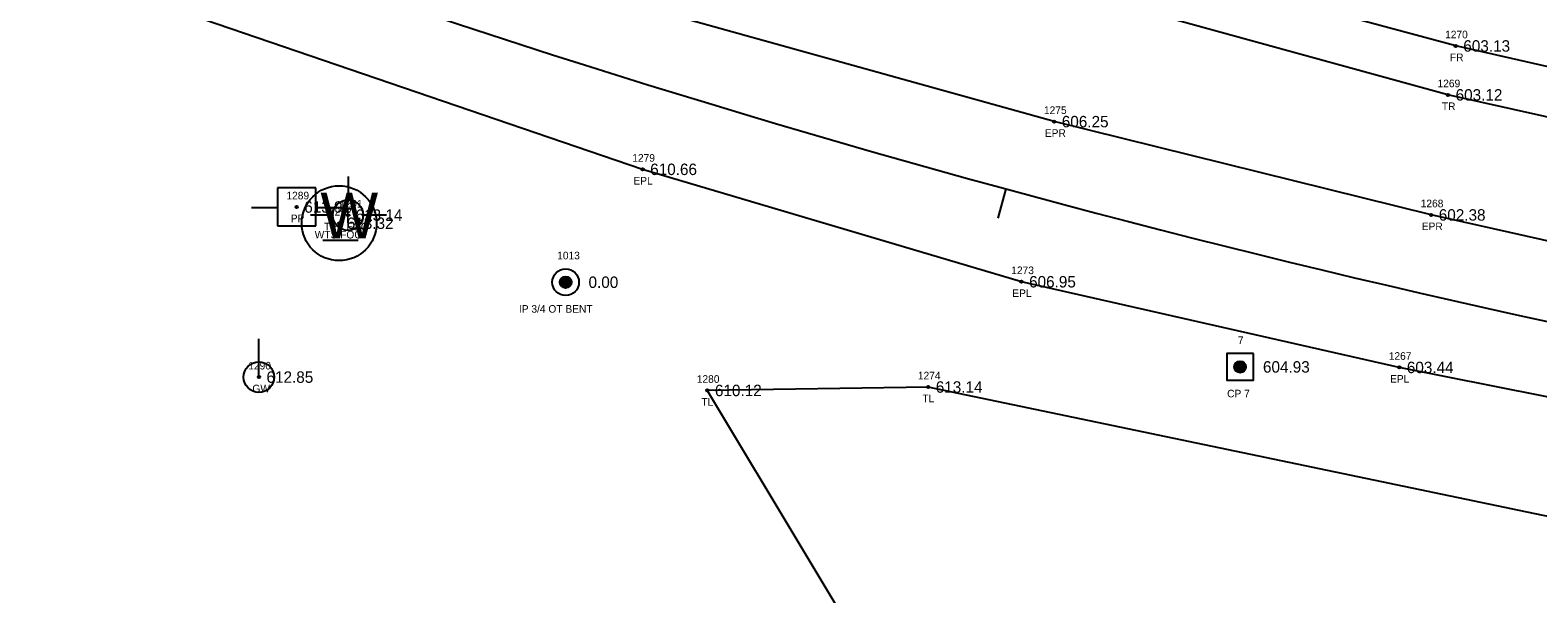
# Model space of a CAD drawing. Extents: x 1529475 to 1532053, y 876698 to 877911.
# Drawn here: x 1530226.7 to 1530424.5, y 877264.8 to 877338.8 of the extents above; entities that cross this region are included whole.
import ezdxf

# ---------------------------------------------------------------- set-up
doc = ezdxf.new("R2010")
doc.units = 0
for name, color, linetype in [('RD_EX_DV_Prop_txCode', 7, 'Continuous'), ('RD_EX_DV_PropPin', 7, 'Continuous'), ('RD_EX_Fence_Other', 7, 'Continuous'), ('RD_EX_Fence_Other_txCode', 7, 'Continuous'), ('RD_EX_Road', 7, 'Continuous'), ('RD_EX_Road_txCode', 7, 'Continuous'), ('RD_EX_TX_DV_Prop_ELEV', 7, 'Continuous'), ('RD_EX_TX_Fence_Other_ELEV', 7, 'Continuous'), ('RD_EX_TX_Road_ELEV', 7, 'Continuous'), ('RD_EX_TX_UT_ELEV', 7, 'Continuous'), ('RD_EX_TX_VEG_ELEV', 7, 'Continuous'), ('RD_EX_UT', 7, 'Continuous'), ('RD_EX_UT_txCode', 7, 'Continuous'), ('RD_EX_VEG', 7, 'Continuous'), ('RD_EX_VEG_txCode', 7, 'Continuous'), ('RD_HC_Cl', 7, 'Continuous'), ('RD_HC_Data_Tic', 7, 'Continuous'), ('RD_HC_Survey', 7, 'Continuous'), ('RD_HC_Survey_ELEV', 7, 'Continuous'), ('RD_HC_Survey_txCode', 7, 'Continuous'), ('RD_SMD_Locator', 7, 'Continuous')]:
    doc.layers.add(name, color=color, linetype=linetype)

msp = doc.modelspace()

# ---------------------------------------------------------------- linework, layer by layer
at = {"layer": 'RD_EX_DV_PropPin'}
for p, q in [((1530296.22, 877305.5), (1530296.22, 877305.9)), ((1530296.26, 877305.4), (1530296.26, 877306)), ((1530296.29, 877305.33), (1530296.29, 877306.07)), ((1530296.33, 877305.27), (1530296.33, 877306.13)), ((1530296.36, 877305.23), (1530296.36, 877306.17)), ((1530296.4, 877305.18), (1530296.4, 877306.21)), ((1530296.43, 877305.15), (1530296.43, 877306.25)), ((1530296.47, 877305.12), (1530296.47, 877306.28)), ((1530296.5, 877305.09), (1530296.5, 877306.31)), ((1530296.54, 877305.07), (1530296.54, 877306.33)), ((1530296.57, 877305.04), (1530296.57, 877306.36)), ((1530296.61, 877305.02), (1530296.61, 877306.38)), ((1530296.64, 877305.01), (1530296.64, 877306.39)), ((1530296.68, 877304.99), (1530296.68, 877306.41)), ((1530296.71, 877304.98), (1530296.71, 877306.42)), ((1530296.75, 877304.97), (1530296.75, 877306.43)), ((1530296.78, 877304.96), (1530296.78, 877306.44)), ((1530296.82, 877304.95), (1530296.82, 877306.45)), ((1530296.85, 877304.95), (1530296.85, 877306.45)), ((1530296.89, 877304.94), (1530296.89, 877306.46)), ((1530296.92, 877304.94), (1530296.92, 877306.46)), ((1530296.96, 877304.94), (1530296.96, 877306.46)), ((1530296.99, 877304.94), (1530296.99, 877306.46)), ((1530297.03, 877304.94), (1530297.03, 877306.46)), ((1530297.06, 877304.95), (1530297.06, 877306.45)), ((1530297.1, 877304.95), (1530297.1, 877306.45)), ((1530297.13, 877304.96), (1530297.13, 877306.44)), ((1530297.17, 877304.97), (1530297.17, 877306.43)), ((1530297.2, 877304.98), (1530297.2, 877306.42)), ((1530297.24, 877304.99), (1530297.24, 877306.41)), ((1530297.27, 877305.01), (1530297.27, 877306.39)), ((1530297.31, 877305.02), (1530297.31, 877306.38)), ((1530297.34, 877305.04), (1530297.34, 877306.36)), ((1530297.38, 877305.07), (1530297.38, 877306.33)), ((1530297.41, 877305.09), (1530297.41, 877306.31)), ((1530297.45, 877305.12), (1530297.45, 877306.28)), ((1530297.48, 877305.15), (1530297.48, 877306.25)), ((1530297.52, 877305.18), (1530297.52, 877306.21)), ((1530297.55, 877305.23), (1530297.55, 877306.17)), ((1530297.59, 877305.27), (1530297.59, 877306.13)), ((1530297.62, 877305.33), (1530297.62, 877306.07)), ((1530297.66, 877305.4), (1530297.66, 877306)), ((1530297.69, 877305.5), (1530297.69, 877305.9))]:
    msp.add_line(p, q, dxfattribs=at)
for radius in [1.75, 0.761]:
    msp.add_circle((1530296.96, 877305.7), radius, dxfattribs=at)
at = {"layer": 'RD_EX_Fence_Other'}
msp.add_lwpolyline([(1530811.24, 877377.37), (1530859.11, 877317.26), (1530840.03, 877318.28), (1530790.63, 877336.24), (1530780.69, 877332.06), (1530773.35, 877330.36), (1530778.53, 877311.65), (1530751.94, 877310.84), (1530704.94, 877310.7), (1530603.15, 877311.86), (1530564.36, 877314.35), (1530514.23, 877318.81), (1530479.67, 877321.7), (1530413.71, 877336.7), (1530368.16, 877348.99), (1530322.52, 877361.53), (1530309.6, 877379.3), (1530304.43, 877399.7)], dxfattribs=at)
at = {"layer": 'RD_EX_Road'}
for points in [[(1530865.35, 877283.66), (1530865.36, 877280.61), (1530815.01, 877277.89), (1530763.54, 877277.33), (1530711.24, 877277.01), (1530660.64, 877277.93), (1530609.51, 877281.74), (1530559.88, 877286.96), (1530511.03, 877294.4), (1530460.35, 877303.35), (1530410.49, 877314.53), (1530361.04, 877326.77), (1530310.59, 877340.83), (1530305.81, 877342.41), (1530288.71, 877347.95), (1530253.55, 877359.27), (1530192.32, 877382.67)], [(1530866.41, 877261.44), (1530852.87, 877260.97), (1530806.23, 877259.4), (1530762.44, 877259.05), (1530711.8, 877259.77), (1530659.89, 877260.87), (1530608.32, 877263.5), (1530557.85, 877268.33), (1530507.29, 877275.71), (1530456.72, 877284.51), (1530406.3, 877294.52), (1530356.75, 877305.76), (1530307.05, 877320.51), (1530246, 877341.34), (1530185.26, 877363.97)]]:
    msp.add_lwpolyline(points, dxfattribs=at)
at = {"layer": 'RD_EX_UT'}
for p, q in [((1530268.41, 877319.57), (1530268.41, 877316.5)), ((1530264.17, 877318.08), (1530259.17, 877318.08)), ((1530259.17, 877318.08), (1530259.17, 877313.08)), ((1530264.17, 877313.08), (1530264.17, 877318.08)), ((1530255.73, 877315.51), (1530259.2, 877315.51)), ((1530264.09, 877315.51), (1530267.73, 877315.51)), ((1530259.17, 877313.08), (1530264.17, 877313.08)), ((1530263.48, 877314.52), (1530266.41, 877314.52)), ((1530270.41, 877314.52), (1530273.48, 877314.52)), ((1530265.12, 877311.23), (1530269.75, 877311.23)), ((1530256.72, 877293.25), (1530256.72, 877298.25))]:
    msp.add_line(p, q, dxfattribs=at)
for centre, radius in [((1530267.25, 877313.44), 4.91), ((1530268.41, 877314.5), 2), ((1530256.72, 877293.25), 2)]:
    msp.add_circle(centre, radius, dxfattribs=at)
at = {"layer": 'RD_EX_VEG'}
for points in [[(1530772.69, 877331.81), (1530751.94, 877310.84), (1530704.94, 877310.7), (1530664.32, 877301.01), (1530564.36, 877314.35), (1530547.76, 877305.07), (1530463.97, 877318.83), (1530412.7, 877330.28), (1530367.19, 877342.84), (1530314.9, 877359.43), (1530309.6, 877379.3), (1530295.63, 877400.8)], [(1530806.62, 877154.57), (1530847.57, 877176.32), (1530815.29, 877240.21), (1530607.98, 877245.85), (1530502.71, 877258.91), (1530344.51, 877291.95), (1530315.54, 877291.5), (1530341.13, 877248.83)]]:
    msp.add_lwpolyline(points, dxfattribs=at)
at = {"layer": 'RD_HC_Cl'}
msp.add_arc((1530728.17, 878687.95), 1420, 249.7768, 272.33207, dxfattribs=at)
at = {"layer": 'RD_HC_Data_Tic'}
msp.add_line((1530354.68, 877317.95), (1530353.63, 877314.09), dxfattribs=at)
at = {"layer": 'RD_HC_Survey'}
for p, q in [((1530384.98, 877293.96), (1530384.98, 877295.21)), ((1530385, 877293.95), (1530385, 877295.23)), ((1530385.03, 877293.93), (1530385.03, 877295.24)), ((1530385.05, 877293.92), (1530385.05, 877295.26)), ((1530385.07, 877293.9), (1530385.07, 877295.27)), ((1530385.1, 877293.89), (1530385.1, 877295.28)), ((1530385.12, 877293.88), (1530385.12, 877295.29)), ((1530385.15, 877293.87), (1530385.15, 877295.3)), ((1530385.17, 877293.86), (1530385.17, 877295.31)), ((1530385.2, 877293.85), (1530385.2, 877295.32)), ((1530385.22, 877293.85), (1530385.22, 877295.33)), ((1530385.25, 877293.84), (1530385.25, 877295.34)), ((1530385.27, 877293.83), (1530385.27, 877295.34)), ((1530385.3, 877293.83), (1530385.3, 877295.35)), ((1530385.32, 877293.83), (1530385.32, 877295.35)), ((1530385.35, 877293.82), (1530385.35, 877295.35)), ((1530385.37, 877293.82), (1530385.37, 877295.35)), ((1530385.4, 877293.82), (1530385.4, 877295.36)), ((1530385.42, 877293.82), (1530385.42, 877295.36)), ((1530385.45, 877293.82), (1530385.45, 877295.36)), ((1530385.47, 877293.82), (1530385.47, 877295.36)), ((1530385.5, 877293.82), (1530385.5, 877295.35)), ((1530385.52, 877293.82), (1530385.52, 877295.35)), ((1530385.54, 877293.83), (1530385.54, 877295.35)), ((1530385.57, 877293.83), (1530385.57, 877295.34)), ((1530385.59, 877293.84), (1530385.59, 877295.34)), ((1530385.62, 877293.84), (1530385.62, 877295.33)), ((1530385.64, 877293.85), (1530385.64, 877295.33)), ((1530385.67, 877293.86), (1530385.67, 877295.32)), ((1530385.69, 877293.87), (1530385.69, 877295.31)), ((1530385.72, 877293.88), (1530385.72, 877295.3)), ((1530385.74, 877293.89), (1530385.74, 877295.29)), ((1530385.77, 877293.9), (1530385.77, 877295.28)), ((1530385.79, 877293.91), (1530385.79, 877295.26)), ((1530385.82, 877293.92), (1530385.82, 877295.25)), ((1530385.84, 877293.94), (1530385.84, 877295.24)), ((1530385.87, 877293.96), (1530385.87, 877295.22)), ((1530385.89, 877293.97), (1530385.89, 877295.2)), ((1530384.68, 877294.41), (1530384.68, 877294.77)), ((1530384.7, 877294.33), (1530384.7, 877294.85)), ((1530384.73, 877294.27), (1530384.73, 877294.91)), ((1530384.75, 877294.22), (1530384.75, 877294.96)), ((1530384.78, 877294.17), (1530384.78, 877295)), ((1530384.8, 877294.14), (1530384.8, 877295.04)), ((1530384.83, 877294.11), (1530384.83, 877295.07)), ((1530384.85, 877294.08), (1530384.85, 877295.1)), ((1530384.88, 877294.05), (1530384.88, 877295.13)), ((1530384.9, 877294.03), (1530384.9, 877295.15)), ((1530384.93, 877294), (1530384.93, 877295.17)), ((1530384.95, 877293.98), (1530384.95, 877295.19)), ((1530385.92, 877293.99), (1530385.92, 877295.18)), ((1530385.94, 877294.01), (1530385.94, 877295.16)), ((1530385.97, 877294.04), (1530385.97, 877295.14)), ((1530385.99, 877294.06), (1530385.99, 877295.11)), ((1530386.02, 877294.09), (1530386.02, 877295.08)), ((1530386.04, 877294.12), (1530386.04, 877295.05)), ((1530386.06, 877294.16), (1530386.06, 877295.02)), ((1530386.09, 877294.2), (1530386.09, 877294.98)), ((1530386.11, 877294.24), (1530386.11, 877294.93)), ((1530386.14, 877294.3), (1530386.14, 877294.88)), ((1530386.16, 877294.36), (1530386.16, 877294.81)), ((1530386.19, 877294.48), (1530386.19, 877294.7))]:
    msp.add_line(p, q, dxfattribs=at)
msp.add_lwpolyline([(1530387.18, 877296.34), (1530383.68, 877296.34), (1530383.68, 877292.84), (1530387.18, 877292.84)], close=True, dxfattribs=at)
msp.add_circle((1530385.43, 877294.59), 0.769, dxfattribs=at)
at = {"layer": 'RD_SMD_Locator'}
for centre in [(1530413.71, 877336.7), (1530412.7, 877330.28), (1530361.04, 877326.77), (1530307.05, 877320.51), (1530261.67, 877315.57), (1530267.25, 877313.44), (1530268.41, 877314.5), (1530410.49, 877314.53), (1530296.96, 877305.7), (1530356.75, 877305.76), (1530256.72, 877293.25), (1530385.43, 877294.59), (1530406.3, 877294.52), (1530315.54, 877291.5), (1530344.51, 877291.95)]:
    msp.add_circle(centre, 0.15, dxfattribs=at)

# ---------------------------------------------------------------- texts
at = {"layer": 'RD_EX_DV_Prop_txCode'}
for s, p in [('1013', (1530295.85, 877308.7)), ('IP 3/4 OT BENT', (1530290.83, 877301.7))]:
    msp.add_text(s, height=1, dxfattribs=at).set_placement(p)
at = {"layer": 'RD_EX_Fence_Other_txCode'}
for s, p in [('1270', (1530412.32, 877337.7)), ('FR', (1530412.95, 877334.7))]:
    msp.add_text(s, height=1, dxfattribs=at).set_placement(p)
at = {"layer": 'RD_EX_Road_txCode'}
for s, p in [('1275', (1530359.7, 877327.77)), ('EPR', (1530359.82, 877324.77)), ('1279', (1530305.7, 877321.51)), ('EPL', (1530305.85, 877318.51)), ('1268', (1530409.12, 877315.53)), ('EPR', (1530409.26, 877312.53)), ('1273', (1530355.41, 877306.76)), ('EPL', (1530355.55, 877303.76)), ('1267', (1530404.93, 877295.52)), ('EPL', (1530405.1, 877292.52))]:
    msp.add_text(s, height=1, dxfattribs=at).set_placement(p)
at = {"layer": 'RD_EX_TX_DV_Prop_ELEV'}
msp.add_text('0.00', height=1.5, dxfattribs=at).set_placement((1530299.96, 877304.95))
at = {"layer": 'RD_EX_TX_Fence_Other_ELEV'}
msp.add_text('603.13', height=1.5, dxfattribs=at).set_placement((1530414.71, 877335.95))
at = {"layer": 'RD_EX_TX_Road_ELEV'}
for s, p in [('606.25', (1530362.04, 877326.02)), ('610.66', (1530308.05, 877319.76)), ('602.38', (1530411.49, 877313.78)), ('606.95', (1530357.75, 877305.01)), ('603.44', (1530407.3, 877293.77))]:
    msp.add_text(s, height=1.5, dxfattribs=at).set_placement(p)
at = {"layer": 'RD_EX_TX_UT_ELEV'}
for s, p in [('613.14', (1530269.41, 877313.75)), ('613.32', (1530268.25, 877312.69)), ('612.85', (1530257.72, 877292.5))]:
    msp.add_text(s, height=1.5, dxfattribs=at).set_placement(p)
at = {"layer": 'RD_EX_TX_VEG_ELEV'}
for s, p in [('603.12', (1530413.7, 877329.53)), ('610.12', (1530316.54, 877290.75)), ('613.14', (1530345.51, 877291.2))]:
    msp.add_text(s, height=1.5, dxfattribs=at).set_placement(p)
at = {"layer": 'RD_EX_UT'}
for s, height, p in [('W', 6, (1530264.79, 877311.44)), ('T', 2, (1530267.57, 877313.45))]:
    msp.add_text(s, height=height, dxfattribs=at).set_placement(p)
at = {"layer": 'RD_EX_UT_txCode'}
for s, p in [('1289', (1530260.33, 877316.57)), ('1292', (1530265.91, 877314.44)), ('1291', (1530267.35, 877315.5)), ('PP', (1530260.9, 877313.57)), ('TPP FOC', (1530265.26, 877312.5)), ('WTS FOC', (1530264.04, 877311.44)), ('1290', (1530255.33, 877294.25)), ('GW', (1530255.87, 877291.25))]:
    msp.add_text(s, height=1, dxfattribs=at).set_placement(p)
at = {"layer": 'RD_EX_VEG_txCode'}
for s, p in [('1269', (1530411.33, 877331.28)), ('TR', (1530411.9, 877328.28)), ('1280', (1530314.16, 877292.5)), ('1274', (1530343.16, 877292.95)), ('TL', (1530314.77, 877289.5)), ('TL', (1530343.74, 877289.95))]:
    msp.add_text(s, height=1, dxfattribs=at).set_placement(p)
at = {"layer": 'RD_HC_Survey_ELEV'}
for s, p in [('613.91', (1530262.67, 877314.82)), ('604.93', (1530388.43, 877293.84))]:
    msp.add_text(s, height=1.5, dxfattribs=at).set_placement(p)
at = {"layer": 'RD_HC_Survey_txCode'}
for s, p in [('7', (1530385.14, 877297.59)), ('CP 7', (1530383.73, 877290.59))]:
    msp.add_text(s, height=1, dxfattribs=at).set_placement(p)

doc.saveas('drawing.dxf')
